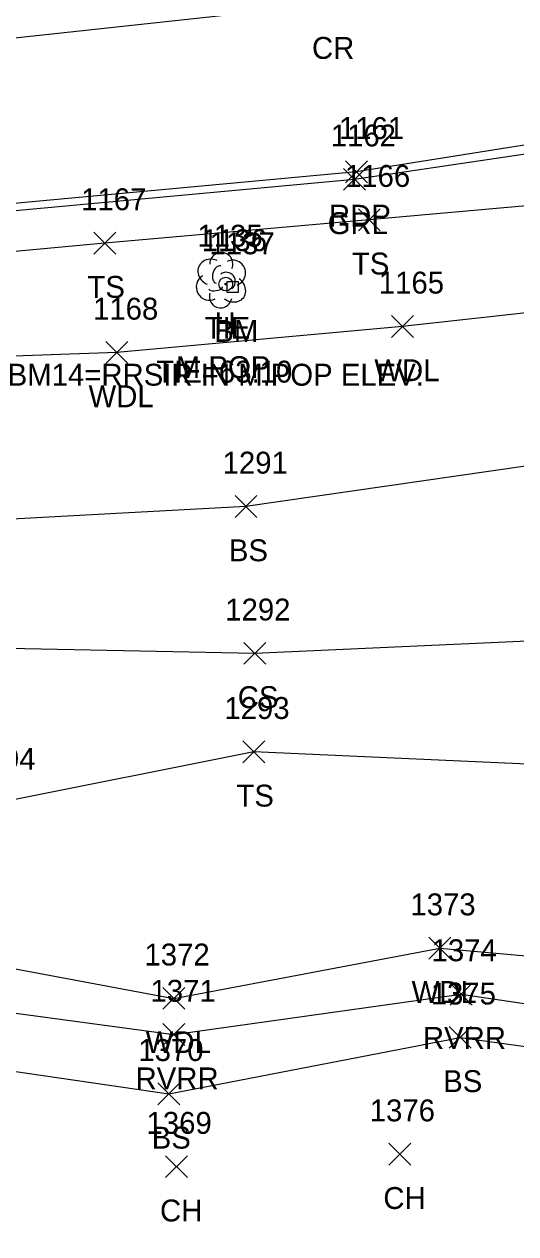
# Model space of a CAD drawing. Extents: x 1502119 to 1504100, y 606168 to 606406.
# Drawn here: x 1503736.1 to 1503780.9, y 606184.3 to 606294.7 of the extents above; entities that cross this region are included whole.
import ezdxf

# ---------------------------------------------------------------- set-up
doc = ezdxf.new("R2010")
doc.units = 0
for name, color, linetype in [('C_A', 7, 'Continuous'), ('C_C', 7, 'Continuous'), ('C_I', 7, 'Continuous'), ('CBP', 7, 'Continuous'), ('CPBM', 7, 'Continuous'), ('L_A', 7, 'Continuous'), ('L_C', 7, 'Continuous'), ('L_I', 7, 'Continuous'), ('L_TIC', 7, 'Continuous'), ('LAWA', 7, 'Continuous'), ('LAWE', 7, 'Continuous'), ('LELB', 7, 'Continuous'), ('LTD', 7, 'Continuous'), ('P_A', 7, 'Continuous'), ('P_I', 7, 'Continuous'), ('P_TIC', 7, 'Continuous'), ('PET', 7, 'Continuous'), ('PRC', 7, 'Continuous'), ('R_A', 7, 'Continuous'), ('R_I', 7, 'Continuous'), ('R_TIC', 7, 'Continuous'), ('RGR', 7, 'Continuous')]:
    doc.layers.add(name, color=color, linetype=linetype)

msp = doc.modelspace()

# ---------------------------------------------------------------- linework, layer by layer
at = {"layer": 'CBP'}
for radius in [0.625, 0.0833]:
    msp.add_circle((1503754.44, 606270.97), radius, dxfattribs=at)
at = {"layer": 'CPBM'}
for p, q in [((1503754.58, 606270.19), (1503754.58, 606271.19)), ((1503754.58, 606271.19), (1503755.58, 606271.19)), ((1503755.58, 606270.19), (1503754.58, 606270.19)), ((1503755.09, 606270.69), (1503755.09, 606270.69)), ((1503755.09, 606270.69), (1503755.09, 606270.69)), ((1503755.58, 606271.19), (1503755.58, 606270.19))]:
    msp.add_line(p, q, dxfattribs=at)
at = {"layer": 'L_TIC'}
for points in [[(1503766.54, 606275.84), (1503768.54, 606277.84)], [(1503768.54, 606275.84), (1503766.54, 606277.84)], [(1503742.42, 606273.71), (1503744.42, 606275.71)], [(1503744.42, 606273.71), (1503742.42, 606275.71)], [(1503769.58, 606266.1), (1503771.58, 606268.1)], [(1503771.58, 606266.1), (1503769.58, 606268.1)], [(1503743.52, 606263.72), (1503745.52, 606265.72)], [(1503745.52, 606263.72), (1503743.52, 606265.72)], [(1503755.29, 606249.66), (1503757.29, 606251.66)], [(1503757.29, 606249.66), (1503755.29, 606251.66)], [(1503756.1, 606236.25), (1503758.1, 606238.25)], [(1503758.1, 606236.25), (1503756.1, 606238.25)], [(1503756.01, 606227.26), (1503758.01, 606229.26)], [(1503758.01, 606227.26), (1503756.01, 606229.26)], [(1503772.98, 606209.33), (1503774.98, 606211.33)], [(1503774.98, 606209.33), (1503772.98, 606211.33)], [(1503748.72, 606204.75), (1503750.72, 606206.75)], [(1503750.72, 606204.75), (1503748.72, 606206.75)], [(1503774.92, 606205.14), (1503776.92, 606207.14)], [(1503776.92, 606205.14), (1503774.92, 606207.14)], [(1503748.7, 606201.44), (1503750.7, 606203.44)], [(1503750.7, 606201.44), (1503748.7, 606203.44)], [(1503774.84, 606201.19), (1503776.84, 606203.19)], [(1503776.84, 606201.19), (1503774.84, 606203.19)], [(1503748.25, 606196.03), (1503750.25, 606198.03)], [(1503750.25, 606196.03), (1503748.25, 606198.03)], [(1503769.33, 606190.52), (1503771.33, 606192.52)], [(1503771.33, 606190.52), (1503769.33, 606192.52)], [(1503748.96, 606189.38), (1503750.96, 606191.38)], [(1503750.96, 606189.38), (1503748.96, 606191.38)]]:
    msp.add_lwpolyline(points, dxfattribs=at)
at = {"layer": 'LAWA'}
for points in [[(1503949.06, 606292.95), (1503922.72, 606291.41), (1503895.88, 606293.14), (1503871.23, 606284.55), (1503848.49, 606280.84), (1503822.63, 606273.75), (1503793.16, 606269.59), (1503770.58, 606267.1), (1503744.52, 606264.72), (1503721.39, 606263.89), (1503714.66, 606265.31), (1503698.22, 606260.24), (1503685.38, 606258.11), (1503660.65, 606259.69), (1503652.68, 606259.1), (1503650.68, 606259.07), (1503643.68, 606257.82), (1503632.11, 606261.1), (1503598.78, 606263.09)], [(1503644.38, 606200.66), (1503661.82, 606197.6), (1503681.92, 606200.3), (1503697.7, 606204.96), (1503718.32, 606211.61), (1503749.72, 606205.75), (1503773.98, 606210.33), (1503804.12, 606207.66), (1503814.72, 606212.71), (1503825.12, 606213.47), (1503835.31, 606218.59), (1503851.96, 606217.91), (1503869.14, 606226.79), (1503894.25, 606229.09), (1503902.71, 606239.52), (1503913.47, 606247.57)]]:
    msp.add_lwpolyline(points, dxfattribs=at)
at = {"layer": 'LAWE'}
msp.add_lwpolyline([(1503614.85, 606213.1), (1503625.62, 606202.51), (1503635.42, 606197.97), (1503642.95, 606193.31), (1503660.89, 606194.04), (1503681.2, 606197.62), (1503698.42, 606201.39), (1503720.62, 606206.39), (1503749.7, 606202.44), (1503775.92, 606206.14), (1503802.08, 606202.28), (1503818.9, 606205.49), (1503835.44, 606207.89), (1503847.03, 606211.3), (1503876.78, 606218.57), (1503896.13, 606221.77), (1503905.66, 606233.48), (1503922.02, 606244.01), (1503934.31, 606243.71)], dxfattribs=at)
at = {"layer": 'LELB'}
for points in [[(1504084.2, 606316.18), (1504049.45, 606313.99), (1504016.18, 606312.8), (1504000.76, 606312.78), (1503990.22, 606311.65), (1503980.1, 606310.35), (1503956.75, 606307.04), (1503915.14, 606300.95), (1503869.77, 606289.77), (1503847.82, 606285.43), (1503820.78, 606281.87), (1503792.45, 606279.04), (1503767.54, 606276.84), (1503743.42, 606274.71), (1503718.48, 606272.4), (1503713.68, 606272.36), (1503654.98, 606271.32), (1503649.47, 606271.35), (1503622.06, 606272.76), (1503601.12, 606274.82)], [(1503984.83, 606255.06), (1503973.29, 606256.69), (1503955.93, 606260.62), (1503952.28, 606267.45), (1503924.4, 606275.03), (1503909.61, 606278), (1503896.78, 606282.99), (1503877.54, 606272.17), (1503862.1, 606272.45), (1503836.9, 606266.22), (1503825.65, 606259.98), (1503818.28, 606261.16), (1503806.2, 606257.22), (1503801.33, 606241.79), (1503784.67, 606238.5), (1503757.1, 606237.25), (1503731.6, 606237.76), (1503710.27, 606237.78), (1503692.02, 606229.45), (1503676.15, 606227.07), (1503663.08, 606221.89), (1503653.08, 606223.12)], [(1503930, 606245.46), (1503918.92, 606249.17), (1503904.84, 606258.51), (1503879.8, 606256.17), (1503860.62, 606251.71), (1503849.74, 606241), (1503840.87, 606237.08), (1503831.29, 606226.33), (1503824.17, 606224.52), (1503818.07, 606222.32), (1503808.71, 606221.45), (1503786.64, 606226.93), (1503757.01, 606228.26), (1503733.84, 606223.62), (1503713.55, 606226.86), (1503694.71, 606218.05), (1503680.4, 606213.07), (1503668.25, 606209.35), (1503648.97, 606211.13)], [(1503818.07, 606222.32), (1503814.66, 606236.26), (1503815.99, 606248.23), (1503806.2, 606257.22), (1503785.15, 606254.84), (1503756.29, 606250.66), (1503730.42, 606249.25), (1503703.2, 606245.4)], [(1503613.71, 606211.71), (1503624.23, 606201.38), (1503628.7, 606194.41), (1503640.82, 606186.16), (1503659.4, 606184.25), (1503680.75, 606191.25), (1503695.72, 606193.45), (1503722.13, 606200.99), (1503749.25, 606197.03), (1503775.84, 606202.19), (1503801.63, 606198.61), (1503818.14, 606200.65), (1503835.99, 606205), (1503847.21, 606209.11), (1503877.12, 606216.19), (1503896.03, 606218.36), (1503907.7, 606226.44), (1503929.55, 606235.83)]]:
    msp.add_lwpolyline(points, dxfattribs=at)
at = {"layer": 'LTD'}
msp.add_line((1503753.99, 606271.38), (1503753.99, 606271.38), dxfattribs=at)
msp.add_line((1503753.99, 606271.38), (1503753.99, 606271.38), dxfattribs=at)
msp.add_arc((1503754.04, 606272.81), 1.05, 335.5272, 180.9563, dxfattribs=at)
for centre, major_axis, ratio, start_param, end_param in [((1503753.2, 606272.04), (1.21, -0.51), 0.895232, 1.570796, 4.712389), ((1503753.78, 606271.83), (-0.208, -0.792), 0.645439, 3.141593, 6.283185), ((1503755.03, 606271.96), (-1.14, -0.48), 0.949671, 1.570796, 4.712389), ((1503752.91, 606270.67), (0.58, -1.04), 0.959034, 3.141593, 6.283185), ((1503754.49, 606271.21), (-0.5, 0.667), 0.989748, 3.141593, 6.283185), ((1503754.99, 606270.54), (-1.09, 0.79), 0.841452, 1.570796, 4.712389), ((1503753.53, 606270.63), (-0.625, -0.083), 0.423636, 0, 3.141593), ((1503753.99, 606269.88), (0.26, 1.06), 0.942809, 1.570796, 4.712389)]:
    msp.add_ellipse(centre, major_axis=major_axis, ratio=ratio, start_param=start_param, end_param=end_param, dxfattribs=at)
at = {"layer": 'P_TIC'}
for points in [[(1503765.38, 606280.21), (1503767.38, 606282.21)], [(1503767.38, 606280.21), (1503765.38, 606282.21)]]:
    msp.add_lwpolyline(points, dxfattribs=at)
at = {"layer": 'PET'}
msp.add_lwpolyline([(1504084.52, 606320.63), (1504050.65, 606320.45), (1504000.43, 606315.8), (1503956.16, 606310.12), (1503915.05, 606304.21), (1503867.85, 606296.91), (1503814.4, 606288.86), (1503766.38, 606281.21), (1503714.75, 606276.43), (1503655.34, 606274.1), (1503622.19, 606275.72), (1503601.58, 606277.52)], dxfattribs=at)
at = {"layer": 'PRC'}
msp.add_lwpolyline([(1504085.68, 606335.47), (1504051.53, 606335.36), (1503999.5, 606331.04), (1503953.49, 606324.86), (1503912.24, 606318.81), (1503865.3, 606311.74), (1503812.8, 606303.34), (1503763.88, 606296.53), (1503711.85, 606290.88), (1503656.36, 606289.42), (1503622.63, 606290.92), (1503602.08, 606292.63)], dxfattribs=at)
at = {"layer": 'R_TIC'}
for points in [[(1503765.2, 606279.53), (1503767.2, 606281.53)], [(1503767.2, 606279.53), (1503765.2, 606281.53)]]:
    msp.add_lwpolyline(points, dxfattribs=at)
at = {"layer": 'RGR'}
msp.add_lwpolyline([(1504084.44, 606319.87), (1504050.55, 606319.53), (1504000.64, 606315), (1503956.05, 606309.11), (1503915.05, 606302.99), (1503867.97, 606295.96), (1503814.82, 606287.72), (1503766.2, 606280.53), (1503714.79, 606275.76), (1503655.19, 606273.62), (1503622.1, 606275.05), (1503601.6, 606277)], dxfattribs=at)

# ---------------------------------------------------------------- texts
at = {"layer": 'C_A'}
for s, p in [('TIE', (1503752.52, 606265.97)), ('BM', (1503753.4, 606265.69))]:
    msp.add_text(s, height=2, dxfattribs=at).set_placement(p)
at = {"layer": 'C_C'}
for s, p in [('BM14=RRSIR IN M.POP ELEV:', (1503734.55, 606261.69)), ('TIE=63.10', (1503748.1, 606261.97))]:
    msp.add_text(s, height=2, dxfattribs=at).set_placement(p)
at = {"layer": 'C_I'}
for s, p in [('1136', (1503752.26, 606273.97)), ('1137', (1503752.96, 606273.69))]:
    msp.add_text(s, height=2, dxfattribs=at).set_placement(p)
at = {"layer": 'L_A'}
for s, p in [('TS', (1503765.95, 606271.84)), ('TS', (1503741.83, 606269.71)), ('H', (1503753.42, 606266.38)), ('WDL', (1503768, 606262.1)), ('WDL', (1503741.93, 606259.72)), ('BS', (1503754.73, 606245.66)), ('CS', (1503755.54, 606232.25)), ('TS', (1503755.42, 606223.26)), ('WDL', (1503771.4, 606205.33)), ('RVRR', (1503772.43, 606201.14)), ('WDL', (1503747.14, 606200.75)), ('RVRR', (1503746.22, 606197.44)), ('BS', (1503774.28, 606197.19)), ('BS', (1503747.69, 606192.03)), ('CH', (1503768.82, 606186.52)), ('CH', (1503748.45, 606185.38))]:
    msp.add_text(s, height=2, dxfattribs=at).set_placement(p)
at = {"layer": 'L_C'}
msp.add_text('M.POP', height=2, dxfattribs=at).set_placement((1503749.89, 606262.38))
at = {"layer": 'L_I'}
for s, p in [('1166', (1503765.32, 606279.84)), ('1167', (1503741.25, 606277.71)), ('1135', (1503751.86, 606274.38)), ('1165', (1503768.41, 606270.1)), ('1168', (1503742.34, 606267.72)), ('1291', (1503754.16, 606253.66)), ('1292', (1503754.4, 606240.25)), ('1293', (1503754.32, 606231.26)), ('1294', (1503731.15, 606226.62)), ('1373', (1503771.29, 606213.33)), ('1372', (1503747.03, 606208.75)), ('1374', (1503773.22, 606209.14)), ('1371', (1503747.58, 606205.44)), ('1375', (1503773.14, 606205.19)), ('1370', (1503746.47, 606200.03)), ('1376', (1503767.58, 606194.52)), ('1369', (1503747.22, 606193.38))]:
    msp.add_text(s, height=2, dxfattribs=at).set_placement(p)
at = {"layer": 'P_A'}
for s, p in [('CR', (1503762.31, 606291.53)), ('RDP', (1503763.86, 606276.21))]:
    msp.add_text(s, height=2, dxfattribs=at).set_placement(p)
at = {"layer": 'P_I'}
msp.add_text('1161', height=2, dxfattribs=at).set_placement((1503764.77, 606284.21))
at = {"layer": 'R_A'}
msp.add_text('GRL', height=2, dxfattribs=at).set_placement((1503763.74, 606275.53))
at = {"layer": 'R_I'}
msp.add_text('1162', height=2, dxfattribs=at).set_placement((1503764.02, 606283.53))

doc.saveas('drawing.dxf')
